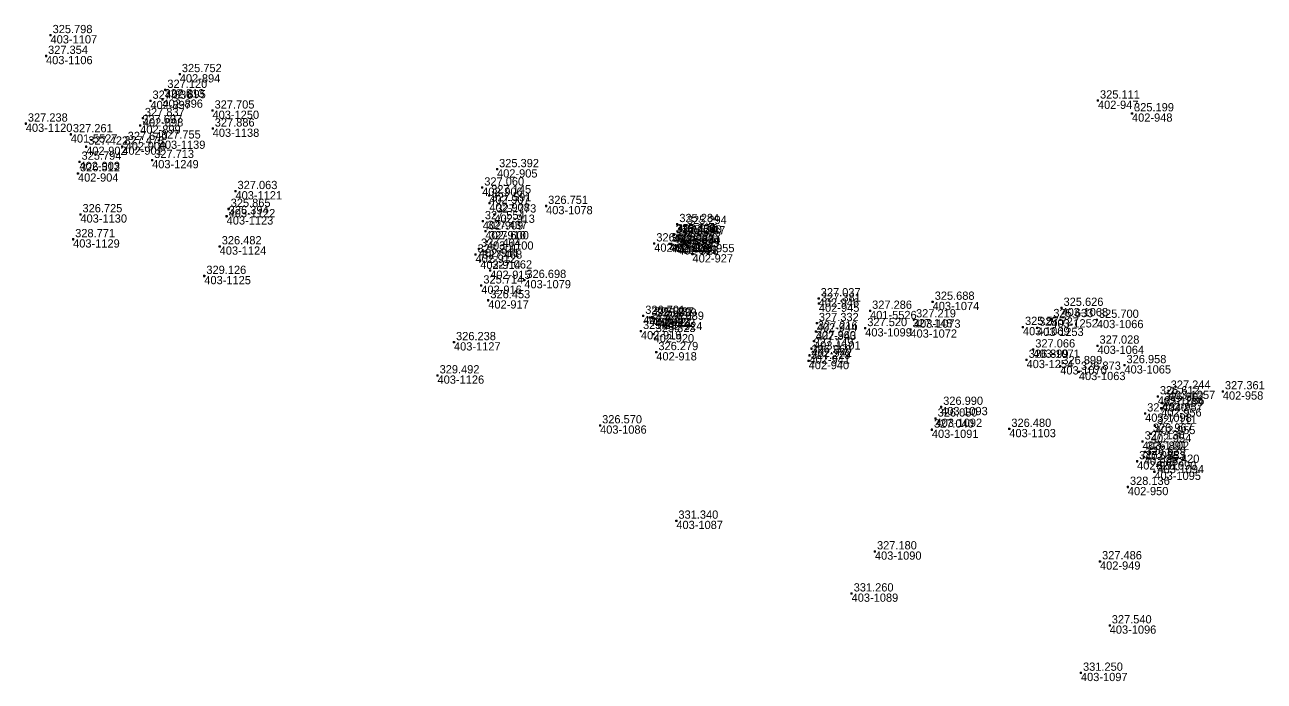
# Model space of a CAD drawing. Extents: x -829398 to -819400, y -1074439 to -1067977.
# Drawn here: x -825480.6 to -825300.2, y -1069493.6 to -1069398 of the extents above; entities that cross this region are included whole.
import ezdxf

# ---------------------------------------------------------------- set-up
doc = ezdxf.new("R2010")
doc.units = 0
for name, color, linetype in [('Vrstva 60', 7, 'Continuous'), ('Vrstva 61', 7, 'Continuous'), ('Čísla bodů_doměření_2012', 7, 'Continuous')]:
    doc.layers.add(name, color=color, linetype=linetype)

# ---------------------------------------------------------------- blocks, each defined once
blk = doc.blocks.new('BOD')
at = {"layer": 'Čísla bodů_doměření_2012'}
for p, q in [((-0.15, 0), (0.15, 0)), ((0, -0.15), (0, 0.15))]:
    blk.add_line(p, q, dxfattribs=at)

msp = doc.modelspace()

# ---------------------------------------------------------------- block references
at = {"layer": 'Vrstva 60'}
for p in [(-825476.869, -1069399.529), (-825477.528, -1069402.551), (-825458.058, -1069405.204), (-825460.167, -1069407.498), (-825462.331, -1069409.081), (-825460.58, -1069408.886), (-825324.415, -1069409.049), (-825453.297, -1069410.506), (-825319.461, -1069410.913), (-825480.47, -1069412.401), (-825463.82, -1069412.658), (-825463.442, -1069411.61), (-825453.268, -1069413.124), (-825473.922, -1069413.958), (-825465.94, -1069415.08), (-825461.116, -1069414.869), (-825471.684, -1069415.751), (-825466.428, -1069415.73), (-825472.657, -1069417.953), (-825462.089, -1069417.698), (-825472.876, -1069419.639), (-825411.883, -1069419.041), (-825449.952, -1069422.227), (-825414.039, -1069421.707), (-825413.024, -1069422.847), (-825412.998, -1069423.985), (-825472.522, -1069425.606), (-825451.236, -1069425.888), (-825450.948, -1069424.822), (-825412.273, -1069425.636), (-825404.743, -1069424.386), (-825413.955, -1069426.613), (-825385.647, -1069427.031), (-825384.55, -1069427.311), (-825473.584, -1069429.237), (-825413.577, -1069428.03), (-825386.178, -1069428.643), (-825386.149, -1069428.507), (-825385.412, -1069429.115), (-825385.276, -1069428.691), (-825452.254, -1069430.27), (-825414.519, -1069430.623), (-825413.358, -1069429.538), (-825388.999, -1069429.847), (-825386.783, -1069429.886), (-825386.519, -1069429.952), (-825386.51, -1069429.918), (-825385.765, -1069430.137), (-825385.765, -1069430.148), (-825385.518, -1069430.256), (-825415.013, -1069431.459), (-825414.322, -1069432.341), (-825383.424, -1069431.405), (-825454.489, -1069434.575), (-825412.879, -1069433.788), (-825414.173, -1069435.968), (-825407.91, -1069435.166), (-825413.154, -1069438.115), (-825365.068, -1069437.834), (-825348.479, -1069438.34), (-825365.033, -1069438.587), (-825357.586, -1069439.652), (-825329.724, -1069439.226), (-825390.609, -1069440.387), (-825389.703, -1069440.635), (-825389.315, -1069440.652), (-825388.939, -1069440.792), (-825387.875, -1069441.251), (-825365.342, -1069441.446), (-825351.198, -1069440.906), (-825335.336, -1069442.003), (-825333.277, -1069442.107), (-825331.207, -1069440.864), (-825324.573, -1069440.966), (-825390.938, -1069442.591), (-825389.09, -1069443.029), (-825365.5, -1069442.659), (-825358.291, -1069442.175), (-825351.713, -1069442.347), (-825418.148, -1069444.218), (-825388.697, -1069445.664), (-825366.114, -1069445.15), (-825365.746, -1069444.075), (-825333.838, -1069445.28), (-825324.487, -1069444.721), (-825366.524, -1069446.938), (-825366.398, -1069446.126), (-825334.805, -1069446.784), (-825420.539, -1069449.054), (-825329.903, -1069447.708), (-825327.19, -1069448.527), (-825320.56, -1069447.571), (-825315.708, -1069452.1), (-825314.13, -1069451.284), (-825306.24, -1069451.374), (-825347.243, -1069453.632), (-825317.551, -1069454.597), (-825315.213, -1069453.835), (-825315.058, -1069453.038), (-825396.884, -1069456.325), (-825348.055, -1069455.334), (-825316.125, -1069456.388), (-825348.588, -1069456.944), (-825337.319, -1069456.84), (-825316.722, -1069457.553), (-825317.927, -1069458.67), (-825317.561, -1069460.167), (-825318.718, -1069461.547), (-825317.736, -1069460.919), (-825316.209, -1069463.058), (-825315.758, -1069462.07), (-825320.06, -1069465.282), (-825385.782, -1069470.204), (-825356.879, -1069474.67), (-825324.12, -1069476.116), (-825360.272, -1069480.793), (-825322.706, -1069485.441), (-825326.891, -1069492.337)]:
    msp.add_blockref('BOD', p, dxfattribs=at)

# ---------------------------------------------------------------- texts
for s, p in [('403-1107', (-825476.869, -1069400.729)), ('403-1106', (-825477.528, -1069403.751)), ('402-894', (-825458.058, -1069406.404)), ('402-895', (-825460.167, -1069408.698)), ('402-897', (-825462.331, -1069410.281)), ('402-896', (-825460.58, -1069410.086)), ('402-947', (-825324.415, -1069410.249)), ('403-1250', (-825453.297, -1069411.706)), ('402-948', (-825319.461, -1069412.113)), ('403-1120', (-825480.47, -1069413.601)), ('402-899', (-825463.82, -1069413.858)), ('402-898', (-825463.442, -1069412.81)), ('403-1138', (-825453.268, -1069414.324)), ('401-5527', (-825473.922, -1069415.158)), ('403-1139', (-825461.116, -1069416.069)), ('402-902', (-825471.684, -1069416.951)), ('402-901', (-825466.428, -1069416.93)), ('402-900', (-825465.94, -1069416.28)), ('402-903', (-825472.657, -1069419.153)), ('403-1249', (-825462.089, -1069418.898)), ('402-904', (-825472.876, -1069420.839)), ('402-905', (-825411.883, -1069420.241)), ('402-906', (-825414.039, -1069422.907)), ('403-1121', (-825449.952, -1069423.427)), ('402-907', (-825413.024, -1069424.047)), ('403-1130', (-825472.522, -1069426.806)), ('403-1122', (-825450.948, -1069426.022)), ('402-908', (-825412.998, -1069425.185)), ('402-913', (-825412.273, -1069426.836)), ('403-1078', (-825404.743, -1069425.586)), ('403-1123', (-825451.236, -1069427.088)), ('402-909', (-825413.955, -1069427.813)), ('402-936', (-825385.647, -1069428.231)), ('402-937', (-825384.55, -1069428.511)), ('403-1129', (-825473.584, -1069430.437)), ('402-910', (-825413.577, -1069429.23)), ('402-932', (-825386.178, -1069429.843)), ('402-933', (-825386.149, -1069429.707)), ('402-935', (-825385.412, -1069430.315)), ('402-934', (-825385.276, -1069429.891)), ('403-1124', (-825452.254, -1069431.47)), ('402-911', (-825414.519, -1069431.823)), ('403-1100', (-825413.358, -1069430.738)), ('402-926', (-825388.999, -1069431.047)), ('402-929', (-825386.783, -1069431.086)), ('402-938', (-825386.519, -1069431.152)), ('402-930', (-825386.51, -1069431.118)), ('402-939', (-825385.765, -1069431.337)), ('402-931', (-825385.765, -1069431.348)), ('402-928', (-825385.518, -1069431.456)), ('402-912', (-825415.013, -1069432.659)), ('402-914', (-825414.322, -1069433.541)), ('402-927', (-825383.424, -1069432.605)), ('403-1125', (-825454.489, -1069435.775)), ('402-915', (-825412.879, -1069434.988)), ('402-916', (-825414.173, -1069437.168)), ('403-1079', (-825407.91, -1069436.366)), ('402-917', (-825413.154, -1069439.315)), ('402-946', (-825365.068, -1069439.034)), ('403-1074', (-825348.479, -1069439.54)), ('402-945', (-825365.033, -1069439.787)), ('401-5526', (-825357.586, -1069440.852)), ('403-1068', (-825329.724, -1069440.426)), ('402-925', (-825390.609, -1069441.587)), ('402-923', (-825389.703, -1069441.835)), ('402-921', (-825389.315, -1069441.852)), ('402-922', (-825388.939, -1069441.992)), ('402-924', (-825387.875, -1069442.451)), ('402-944', (-825365.342, -1069442.646)), ('403-1073', (-825351.198, -1069442.106)), ('403-1069', (-825335.336, -1069443.203)), ('403-1252', (-825331.207, -1069442.064)), ('403-1066', (-825324.573, -1069442.166)), ('402-919', (-825390.938, -1069443.791)), ('402-920', (-825389.09, -1069444.229)), ('402-943', (-825365.5, -1069443.859)), ('403-1099', (-825358.291, -1069443.375)), ('403-1072', (-825351.713, -1069443.547)), ('403-1253', (-825333.277, -1069443.307)), ('403-1127', (-825418.148, -1069445.418)), ('402-942', (-825366.114, -1069446.35)), ('403-1101', (-825365.746, -1069445.275)), ('403-1071', (-825333.838, -1069446.48)), ('403-1064', (-825324.487, -1069445.921)), ('402-918', (-825388.697, -1069446.864)), ('402-940', (-825366.524, -1069448.138)), ('402-941', (-825366.398, -1069447.326)), ('403-1254', (-825334.805, -1069447.984)), ('403-1126', (-825420.539, -1069450.254)), ('403-1070', (-825329.903, -1069448.908)), ('403-1063', (-825327.19, -1069449.727)), ('403-1065', (-825320.56, -1069448.771)), ('403-1256', (-825315.708, -1069453.3)), ('403-1257', (-825314.13, -1069452.484)), ('402-958', (-825306.24, -1069452.574)), ('403-1093', (-825347.243, -1069454.832)), ('403-1098', (-825317.551, -1069455.797)), ('402-956', (-825315.213, -1069455.035)), ('402-957', (-825315.058, -1069454.238)), ('403-1086', (-825396.884, -1069457.525)), ('403-1092', (-825348.055, -1069456.534)), ('402-955', (-825316.125, -1069457.588)), ('403-1091', (-825348.588, -1069458.144)), ('403-1103', (-825337.319, -1069458.04)), ('402-954', (-825316.722, -1069458.753)), ('403-1102', (-825317.927, -1069459.87)), ('402-951', (-825318.718, -1069462.747)), ('402-952', (-825317.736, -1069462.119)), ('402-953', (-825317.561, -1069461.367)), ('403-1095', (-825316.209, -1069464.258)), ('403-1094', (-825315.758, -1069463.27)), ('402-950', (-825320.06, -1069466.482)), ('403-1087', (-825385.782, -1069471.404)), ('403-1090', (-825356.879, -1069475.87)), ('402-949', (-825324.12, -1069477.316)), ('403-1089', (-825360.272, -1069481.993)), ('403-1096', (-825322.706, -1069486.641)), ('403-1097', (-825326.891, -1069493.537))]:
    msp.add_text(s, height=1.2, dxfattribs=at).set_placement(p)
at = {"layer": 'Vrstva 61'}
for s, p in [('325.798', (-825476.569, -1069399.229)), ('327.354', (-825477.228, -1069402.251)), ('325.752', (-825457.758, -1069404.904)), ('327.836', (-825462.031, -1069408.781)), ('327.513', (-825460.28, -1069408.586)), ('327.120', (-825459.867, -1069407.198)), ('325.111', (-825324.115, -1069408.749)), ('327.705', (-825452.997, -1069410.206)), ('325.199', (-825319.161, -1069410.613)), ('327.238', (-825480.17, -1069412.101)), ('327.697', (-825463.52, -1069412.358)), ('327.837', (-825463.142, -1069411.31)), ('327.261', (-825473.622, -1069413.658)), ('327.886', (-825452.968, -1069412.824)), ('327.422', (-825471.384, -1069415.451)), ('327.473', (-825466.128, -1069415.43)), ('327.640', (-825465.64, -1069414.78)), ('327.755', (-825460.816, -1069414.569)), ('325.794', (-825472.357, -1069417.653)), ('327.713', (-825461.789, -1069417.398)), ('326.512', (-825472.576, -1069419.339)), ('325.392', (-825411.583, -1069418.741)), ('327.060', (-825413.739, -1069421.407)), ('327.063', (-825449.652, -1069421.927)), ('327.145', (-825412.724, -1069422.547)), ('325.865', (-825450.648, -1069424.522)), ('327.591', (-825412.698, -1069423.685)), ('326.751', (-825404.443, -1069424.086)), ('326.725', (-825472.222, -1069425.306)), ('326.394', (-825450.936, -1069425.588)), ('327.554', (-825413.655, -1069426.313)), ('327.773', (-825411.973, -1069425.336)), ('325.284', (-825385.347, -1069426.731)), ('327.437', (-825413.277, -1069427.73)), ('325.453', (-825385.878, -1069428.343)), ('325.230', (-825385.849, -1069428.207)), ('325.240', (-825384.976, -1069428.391)), ('325.294', (-825384.25, -1069427.011)), ('328.771', (-825473.284, -1069428.937)), ('326.482', (-825451.954, -1069429.97)), ('327.404', (-825414.219, -1069430.323)), ('327.600', (-825413.058, -1069429.238)), ('326.958', (-825388.699, -1069429.547)), ('326.357', (-825386.483, -1069429.586)), ('325.050', (-825386.219, -1069429.652)), ('326.160', (-825386.21, -1069429.618)), ('325.101', (-825385.465, -1069429.837)), ('326.150', (-825385.465, -1069429.848)), ('326.380', (-825385.218, -1069429.956)), ('325.556', (-825385.112, -1069428.815)), ('327.201', (-825414.713, -1069431.159)), ('327.468', (-825414.022, -1069432.041)), ('326.955', (-825383.124, -1069431.105)), ('327.062', (-825412.579, -1069433.488)), ('329.126', (-825454.189, -1069434.275)), ('325.714', (-825413.873, -1069435.668)), ('326.698', (-825407.61, -1069434.866)), ('327.037', (-825364.768, -1069437.534)), ('326.453', (-825412.854, -1069437.815)), ('327.381', (-825364.733, -1069438.287)), ('327.286', (-825357.286, -1069439.352)), ('325.688', (-825348.179, -1069438.04)), ('325.626', (-825329.424, -1069438.926)), ('326.701', (-825390.309, -1069440.087)), ('325.830', (-825389.403, -1069440.335)), ('325.437', (-825389.015, -1069440.352)), ('325.839', (-825388.639, -1069440.492)), ('326.689', (-825387.575, -1069440.951)), ('327.332', (-825365.042, -1069441.146)), ('327.219', (-825350.898, -1069440.606)), ('325.633', (-825330.907, -1069440.564)), ('325.700', (-825324.273, -1069440.666)), ('325.594', (-825390.638, -1069442.291)), ('325.823', (-825388.79, -1069442.729)), ('327.216', (-825365.2, -1069442.359)), ('327.520', (-825357.991, -1069441.875)), ('327.148', (-825351.413, -1069442.047)), ('325.575', (-825335.036, -1069441.703)), ('325.727', (-825332.977, -1069441.807)), ('326.238', (-825417.848, -1069443.918)), ('327.149', (-825365.814, -1069444.85)), ('327.360', (-825365.446, -1069443.775)), ('327.066', (-825333.538, -1069444.98)), ('327.028', (-825324.187, -1069444.421)), ('326.279', (-825388.397, -1069445.364)), ('327.229', (-825366.224, -1069446.638)), ('326.968', (-825366.098, -1069445.826)), ('326.899', (-825334.505, -1069446.484)), ('326.899', (-825329.603, -1069447.408)), ('326.873', (-825326.89, -1069448.227)), ('326.958', (-825320.26, -1069447.271)), ('329.492', (-825420.239, -1069448.754)), ('326.612', (-825315.408, -1069451.8)), ('327.244', (-825313.83, -1069450.984)), ('327.361', (-825305.94, -1069451.074)), ('326.990', (-825346.943, -1069453.332)), ('327.169', (-825314.913, -1069453.535)), ('326.907', (-825314.758, -1069452.738)), ('326.080', (-825347.755, -1069455.034)), ('327.340', (-825317.251, -1069454.297)), ('326.570', (-825396.584, -1069456.025)), ('327.040', (-825348.288, -1069456.644)), ('326.480', (-825337.019, -1069456.54)), ('326.967', (-825316.422, -1069457.253)), ('327.111', (-825315.825, -1069456.088)), ('327.130', (-825317.627, -1069458.37)), ('327.035', (-825318.418, -1069461.247)), ('326.639', (-825317.436, -1069460.619)), ('326.891', (-825317.261, -1069459.867)), ('326.090', (-825315.909, -1069462.758)), ('326.420', (-825315.458, -1069461.77)), ('328.136', (-825319.76, -1069464.982)), ('331.340', (-825385.482, -1069469.904)), ('327.180', (-825356.579, -1069474.37)), ('327.486', (-825323.82, -1069475.816)), ('331.260', (-825359.972, -1069480.493)), ('327.540', (-825322.406, -1069485.141)), ('331.250', (-825326.591, -1069492.037))]:
    msp.add_text(s, height=1.2, dxfattribs=at).set_placement(p)

doc.saveas('drawing.dxf')
